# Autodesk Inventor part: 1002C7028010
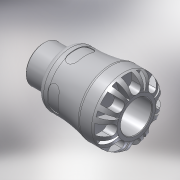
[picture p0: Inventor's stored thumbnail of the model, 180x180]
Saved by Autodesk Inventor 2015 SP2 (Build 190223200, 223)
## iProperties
Created: 2016-12
Part Number: 1002C7028010
Material: PVC-Piping
Description: PLASSON MALE COPPER ADAPTOR 28X1" SERIES 1
Document SubType Name: Modeling
Designer: KIM
Mass: 78.119 g
Surface Area: 135.648 cm^2
Volume: 55.7993 cm^3
Density: 1.4 g/cm^3
Appearance: Smooth - White
Author: KIM
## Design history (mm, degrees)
derived "1002С.ipt"
feature "Solid1::1002С.ipt"
tag "TaggingFeature1"
body "Solid1"
other parameters: "d0" = 84, "d1" = 23.1, "d2" = 28, "d3" = 34.8, "d4" = 58, "d6" = 55, "d8" = 49.3, "d13" = 9.28, "d14" = 9.28, "d15" = 0, "d17" = 360 deg, "d19" = 8 deg, "d20" = 0.56, "d21" = 0.56, "d22" = 8 deg, "d24" = 0, "d26" = 360 deg, "d32" = 5.8, "d33" = 5.8, "d34" = 33.249, "d35" = 3.5, "d38" = 19, "d39" = 0.99747, "d42" = 9.86, "d43" = 6.38, "d45" = 18.032, "d46" = 0, "d59" = 360 deg, "d62" = 8.381, "d63" = 0.56, "d65" = 0, "d66" = 0.58, "d_" = 28, "E_" = 58, "H_" = 84, "l_" = 55, "R_" = 33.249, "l_2" = 19, "d9" = 11.6, "d11" = 58, "d12" = 34.8
